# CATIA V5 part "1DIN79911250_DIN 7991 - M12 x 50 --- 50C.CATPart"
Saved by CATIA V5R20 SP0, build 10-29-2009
Part number: 1DIN79911250_DIN 7991 - M12 x 50 --- 50C
Revision: ANY
Definition: UNKNOWN
Nomenclature: 1DIN79911250_DIN 7991 - M12 x 50 --- 50C
Source: Unknown
Bounding box of the stored display mesh (mm): x 0 to 50, y -11.562 to 11.562, z -11.74 to 11.74
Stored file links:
  C:\Users\Utente\Desktop\IO LAVORO\3D X SITO CF\CUMSA\3D files RC\RC 328016\1DIN79911250_DIN 7991 - M12 x 50 --- 50C.CATPart
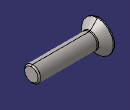
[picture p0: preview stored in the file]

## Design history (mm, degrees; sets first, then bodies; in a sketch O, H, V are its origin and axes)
Body1 "Hex" (main body)
  Solid1: solid without history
